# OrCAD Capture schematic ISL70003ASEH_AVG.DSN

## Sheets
1 PAGE1: size B
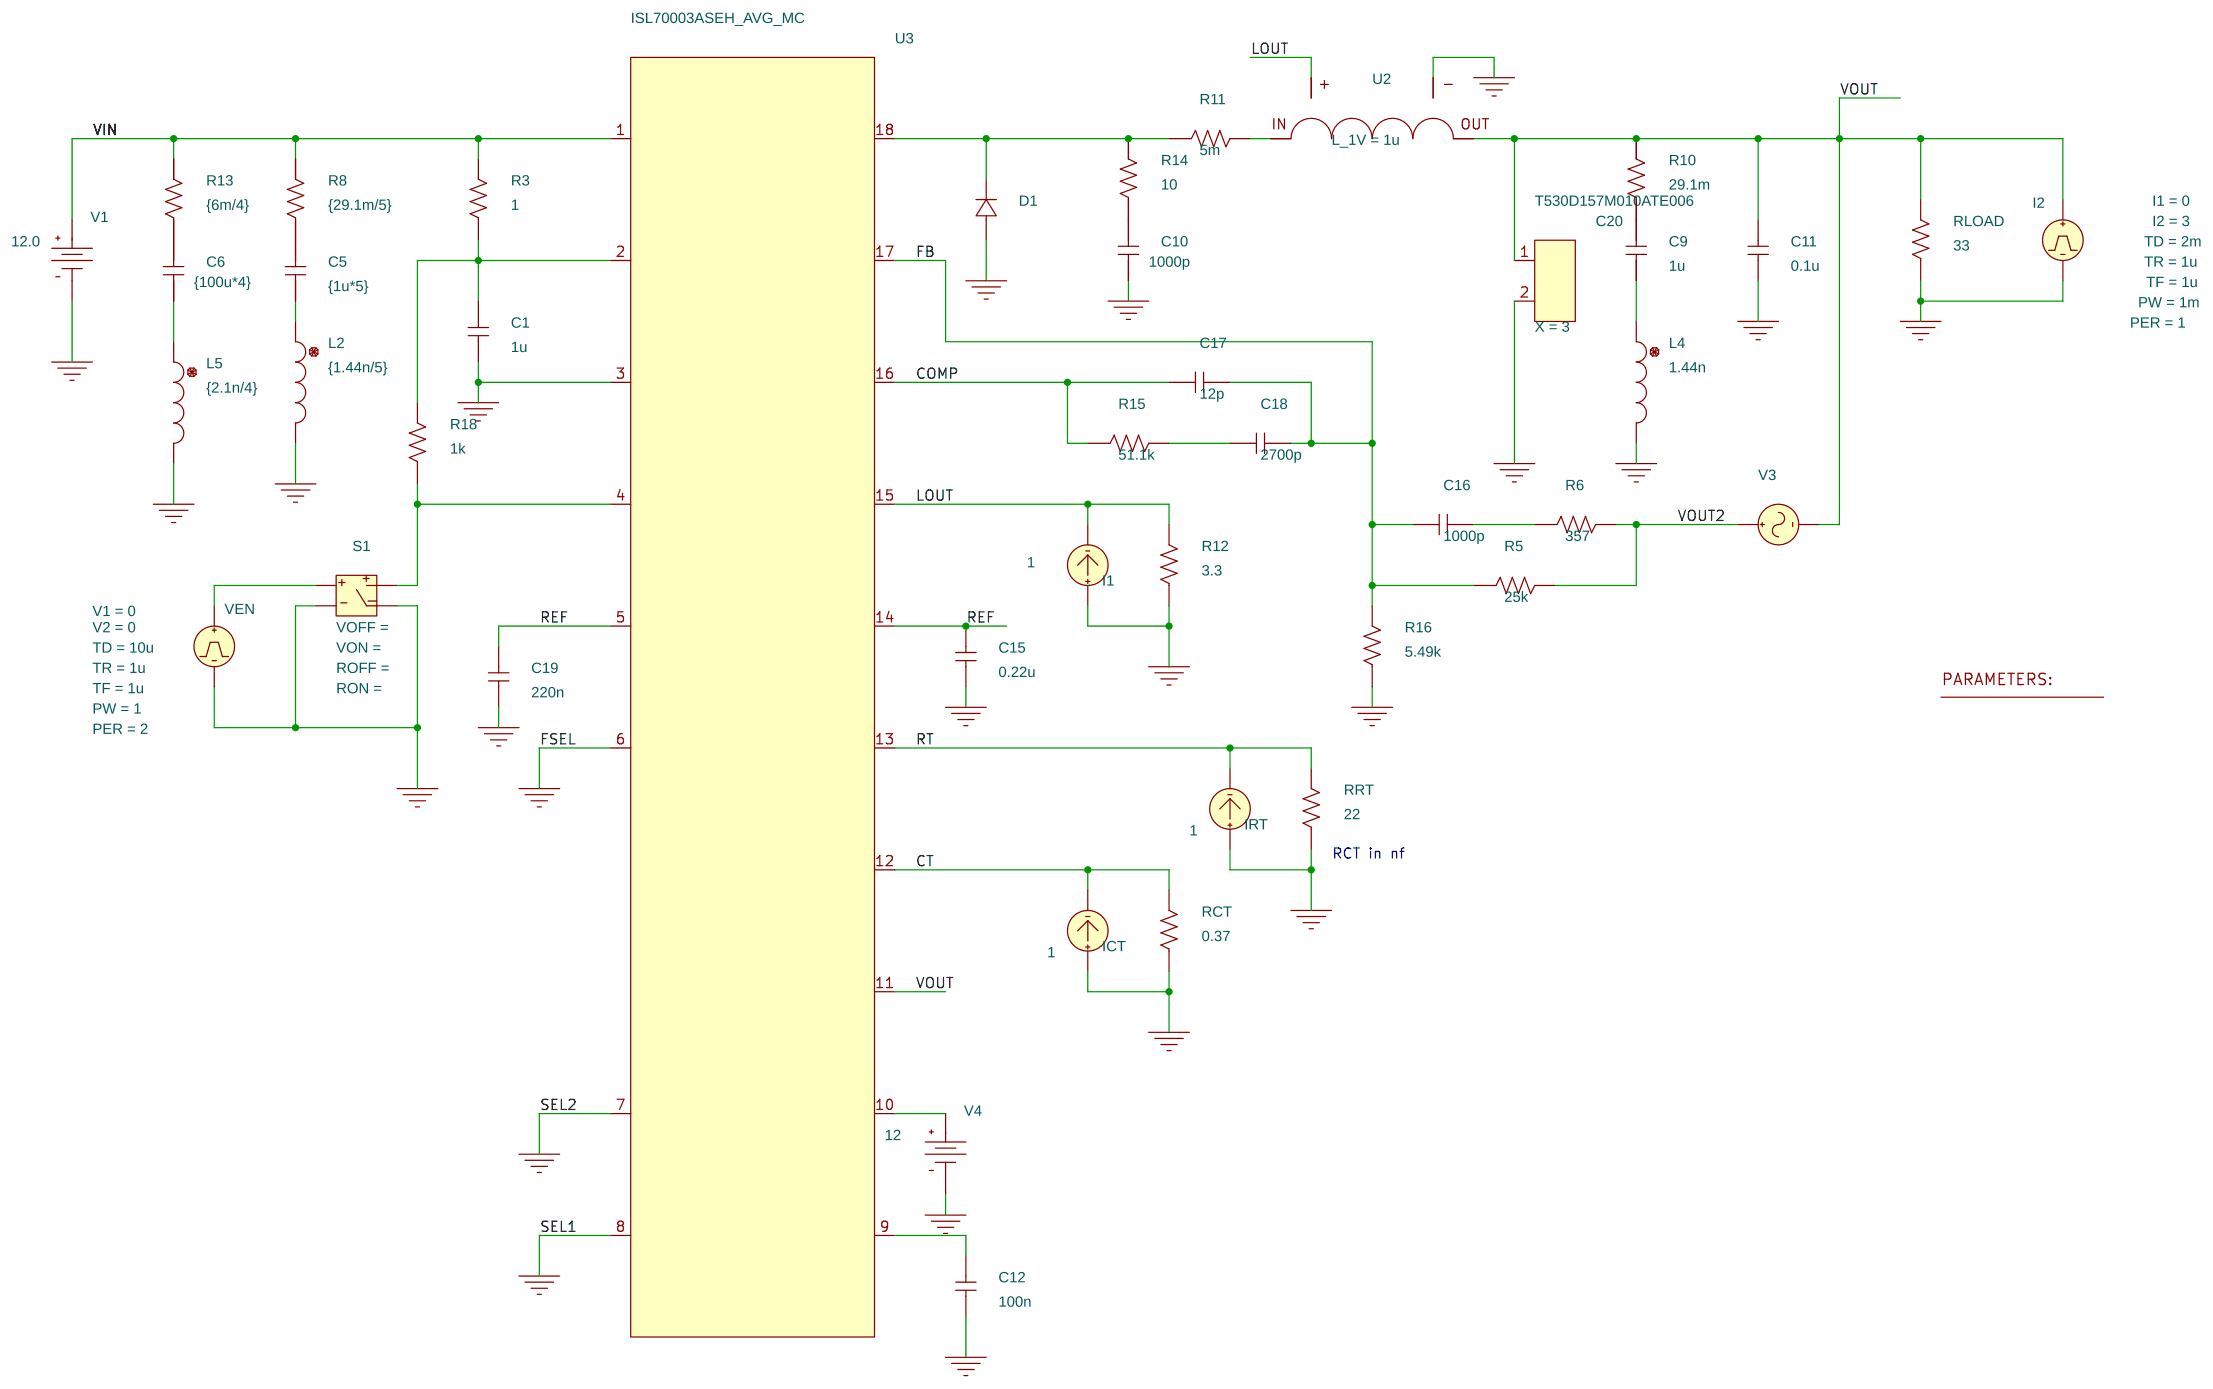
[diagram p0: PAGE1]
2 PAGE1 (2)
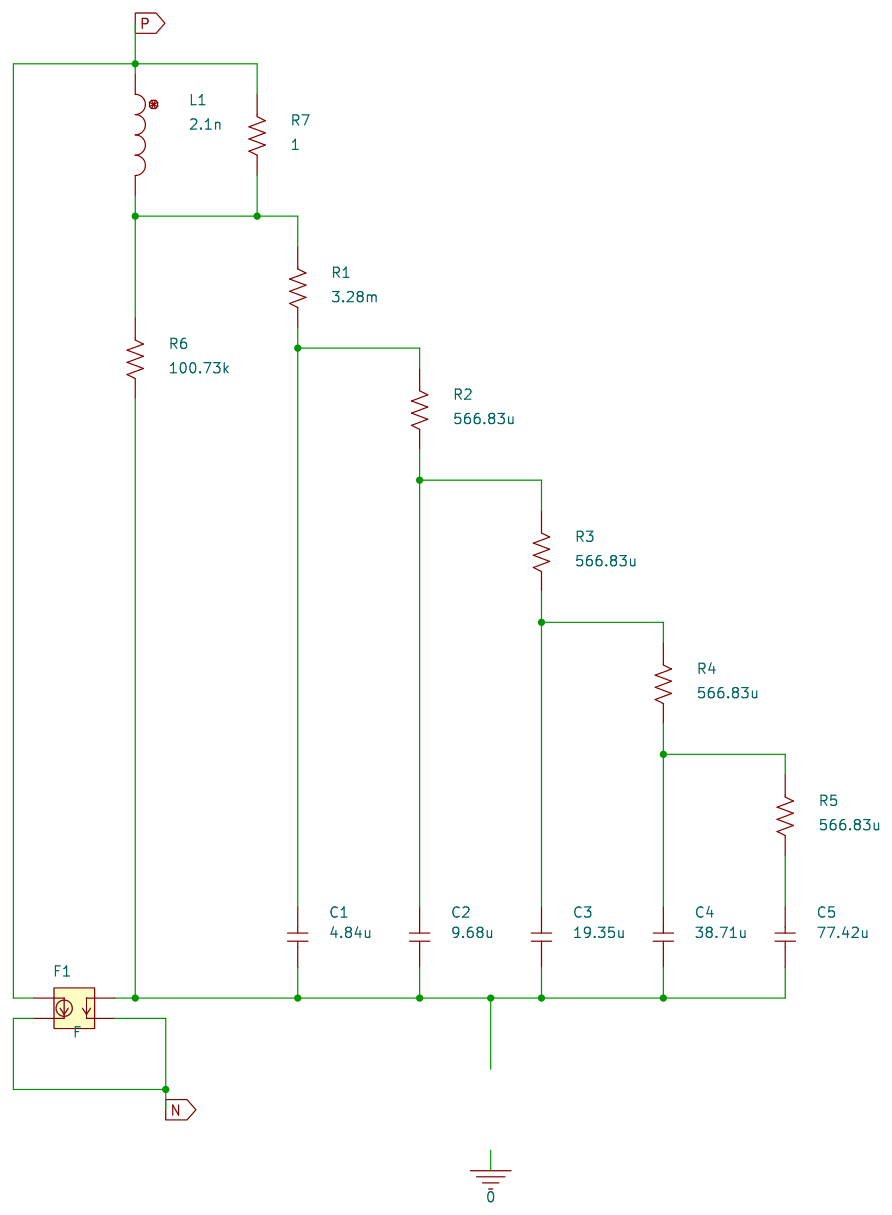
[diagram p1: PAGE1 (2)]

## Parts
sheet PAGE1 (2)
C1  4.84u  [cap196]
C2  9.68u  [cap196]
C3  19.35u  [cap196]
C4  38.71u  [cap196]
C5  77.42u  [cap196]
F1  F
L1  2.1n  [DISC350x175LS200x100034]
R1  3.28m  [AX/RC05]
R2  566.83u  [AX/RC05]
R3  566.83u  [AX/RC05]
R4  566.83u  [AX/RC05]
R5  566.83u  [AX/RC05]
R6  100.73k  [AX/RC05]
R7  1  [AX/RC05]
sheet PAGE1
3  PARAM
C6  {100u*4}  [RAD/CK05]
C9  1u  [RAD/CK05]
C10  1000p  [RAD/CK05]
C11  0.1u  [RAD/CK05]
C12  100n  [RAD/CK05]
C15  0.22u  [RAD/CK05]
C16  1000p  [RAD/CK05]
C17  12p  [RAD/CK05]
C18  2700p  [RAD/CK05]
C19  220n  [RAD/CK05]
C20  T530D157M010ATE006
D1  DMBR2045CTP/ON
I1  IDC
I2  IPULSE
ICT  IDC
IRT  IDC
L2  {1.44n/5}  [DISC/.350x.175/LS.200x.100/.034]
L4  1.44n  [DISC/.350x.175/LS.200x.100/.034]
L5  {2.1n/4}  [DISC/.350x.175/LS.200x.100/.034]
R8  {29.1m/5}  [AX/RC05]
R10  29.1m  [AX/RC05]
R11  5m  [AX/RC05]
R12  3.3  [AX/RC05]
R13  {6m/4}  [AX/RC05]
R14  10  [AX/RC05]
R15  51.1k  [AX/RC05]
R16  5.49k  [AX/RC05]
R18  1k  [AX/RC05]
RCT  0.37  [AX/RC05]
RLOAD  33  [AX/RC05]
RRT  22  [AX/RC05]
S1  S
U2  VC_INDUCTOR
U3  ISL70003ASEH_AVG_MC
V1  VDC
V3  VAC
V4  VDC
VEN  VPULSE

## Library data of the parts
C1-C6 C9-C12 C15-C19 = C
F1 = F: GAIN: {X-1}
L1 L2 L4 L5 = L
R1-R8 R10-R16 R18 RCT RLOAD RRT = R
3 = PARAM
C20 = T530D157M010ATE006: X: 3
D1 = DMBR2045CTP_ON
I1 ICT IRT = IDC: DC: 1
I2 = IPULSE: I1: 0; I2: 3; PER: 1; PW: 1m; TD: 2m; TF: 1u; TR: 1u
S1 = S
U2 = VC_INDUCTOR: L_1V: 1u
U3 = ISL70003ASEH_AVG_MC
V1 = VDC: DC: 12.0
V3 = VAC
V4 = VDC: DC: 12
VEN = VPULSE: PER: 2; PW: 1; TD: 10u; TF: 1u; TR: 1u; V1: 0; V2: 0

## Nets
VIN: R3.2 R8.2 R13.2 U3.1(PVIN) V1.0(+)
0: C1.1 C10.1 C11.1 C12.1 C15.1 C19.1 C20.2(N) D1.0(1) I1.1(+) I2.2(-) ICT.1(+) IRT.1(+) L2.2 L4.2 L5.2 R12.1 R16.1 RCT.1 RLOAD.1 RRT.1 S1.1(2) S1.3(4) U2.4 U3.3(PGND) U3.6(FSEL) U3.7(SEL2) U3.8(SEL1) V1.1(-) V4.1(-) VEN.2(-)
COMP: C17.1 R15.1 U3.16(VERR)
CT: ICT.2(-) RCT.2 U3.12(CT)
FB: C16.1 C17.2 C18.2 R5.1 R16.2 U3.17(FB)
LOUT: I1.2(-) R12.2 U2.3 U3.15(LOUT)
N: F1.2 F1.4
P: F1.3 L1.1 R7.1
REF: C15.2 C19.2 U3.5(NI) U3.14(REF)
RT: IRT.2(-) RRT.2 U3.13(RT)
VOUT: C11.2 C20.1(P) I2.1(+) R10.2 RLOAD.2 U2.2 U3.11(VOUT) V3.2(-)
VOUT2: R5.2 R6.2 V3.1(+)
N1938691: D1.1(2) R11.1 R14.2 U3.18(LX)
N1938709: C9.1 L4.1
N1938737: R11.2 U2.1
N1939753: C5.1 L2.1
N1939757: R18.1 S1.2(3) U3.4(ENABLE)
N1939773: C1.2 R3.1 R18.2 U3.2(AVDD)
N1939825: C6.1 L5.1
N1940127: S1.0(1) VEN.1(+)
N1942357: C12.2 U3.9(SS)
N1946417: C16.2 R6.1
N1946563: C18.1 R15.2
N1949405: U3.10(DE) V4.0(+)
N1990193: C6.2 R13.1
N1990195: C10.2 R14.1
N1990196: C9.2 R10.1
N1990197: C5.2 R8.1

Not connected (* = marked no-connect by the designer): C2 1 2; C3 1 2; C4 1 2; F1 1; L1 2; R1 1 2; R2 1 2; R4 1 2; R7 2

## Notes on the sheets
sheet 1
- RCT in nf
